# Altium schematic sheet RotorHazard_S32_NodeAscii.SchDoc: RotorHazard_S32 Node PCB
size A; Revision: 1.0; SheetNumber: 1; SheetTotal: 1
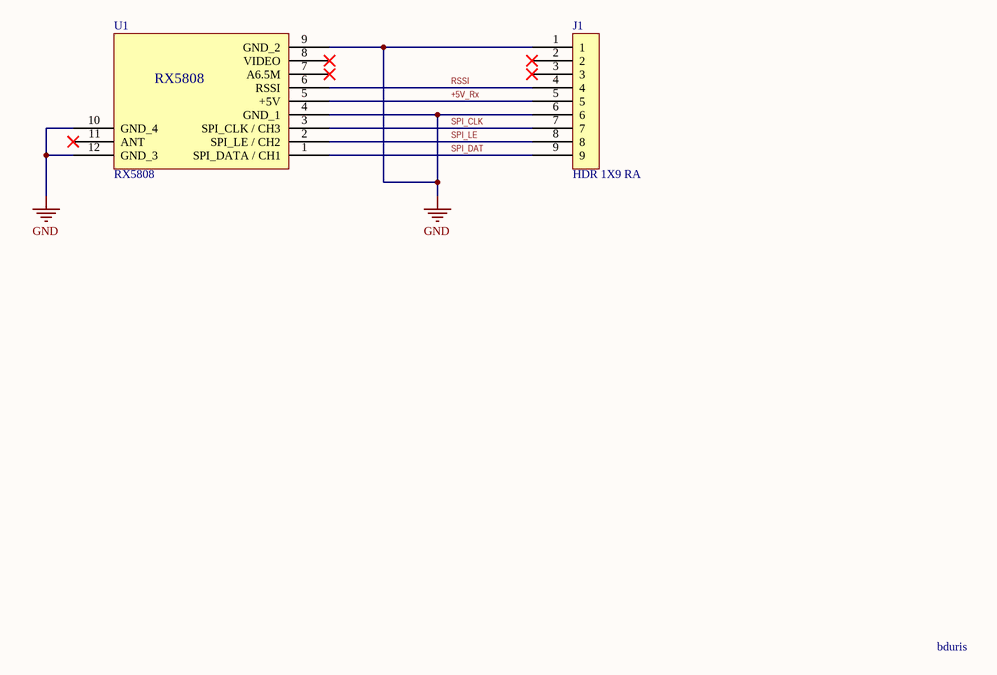
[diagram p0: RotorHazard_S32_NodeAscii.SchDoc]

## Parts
J1  HDR 1X9 RA  [HDR 1X9 2.54mm RA]
U1  RX5808  [RX5808_MULTI]

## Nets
GND: J1.1 J1.6 U1.4(GND_1) U1.9(GND_2) U1.10(GND_4) U1.12(GND_3)
+5V_Rx: J1.5 U1.5(+5V)
RSSI: J1.4 U1.6(RSSI)
SPI_CLK: J1.7 U1.3(SPI_CLK_/_CH3)
SPI_DAT: J1.9 U1.1(SPI_DATA_/_CH1)
SPI_LE: J1.8 U1.2(SPI_LE_/_CH2)

Not connected (* = marked no-connect by the designer): J1 2* 3*; U1 7(A6.5M)* 8(VIDEO)* 11(ANT)*

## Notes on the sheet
- bduris

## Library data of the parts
J1 = 649-1012937990904BLF: 9-Pin RA Header Thru-Hole; Manufacturer: Amphenol FCI; Manufacturer Part Number: 10129379-909004BLF; Current Rating: 3 A; Mounting Angle: Right Angle; Number of Positions: 9 Position; Voltage Rating: 110 V; Pitch: 2.54 mm; Insulation Resistance: 1 GOhms; Mating Post Length: 8.08 mm; Product Status: New Product
U1 = RX5808_MULTI: RX5808 with multi-layer pads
